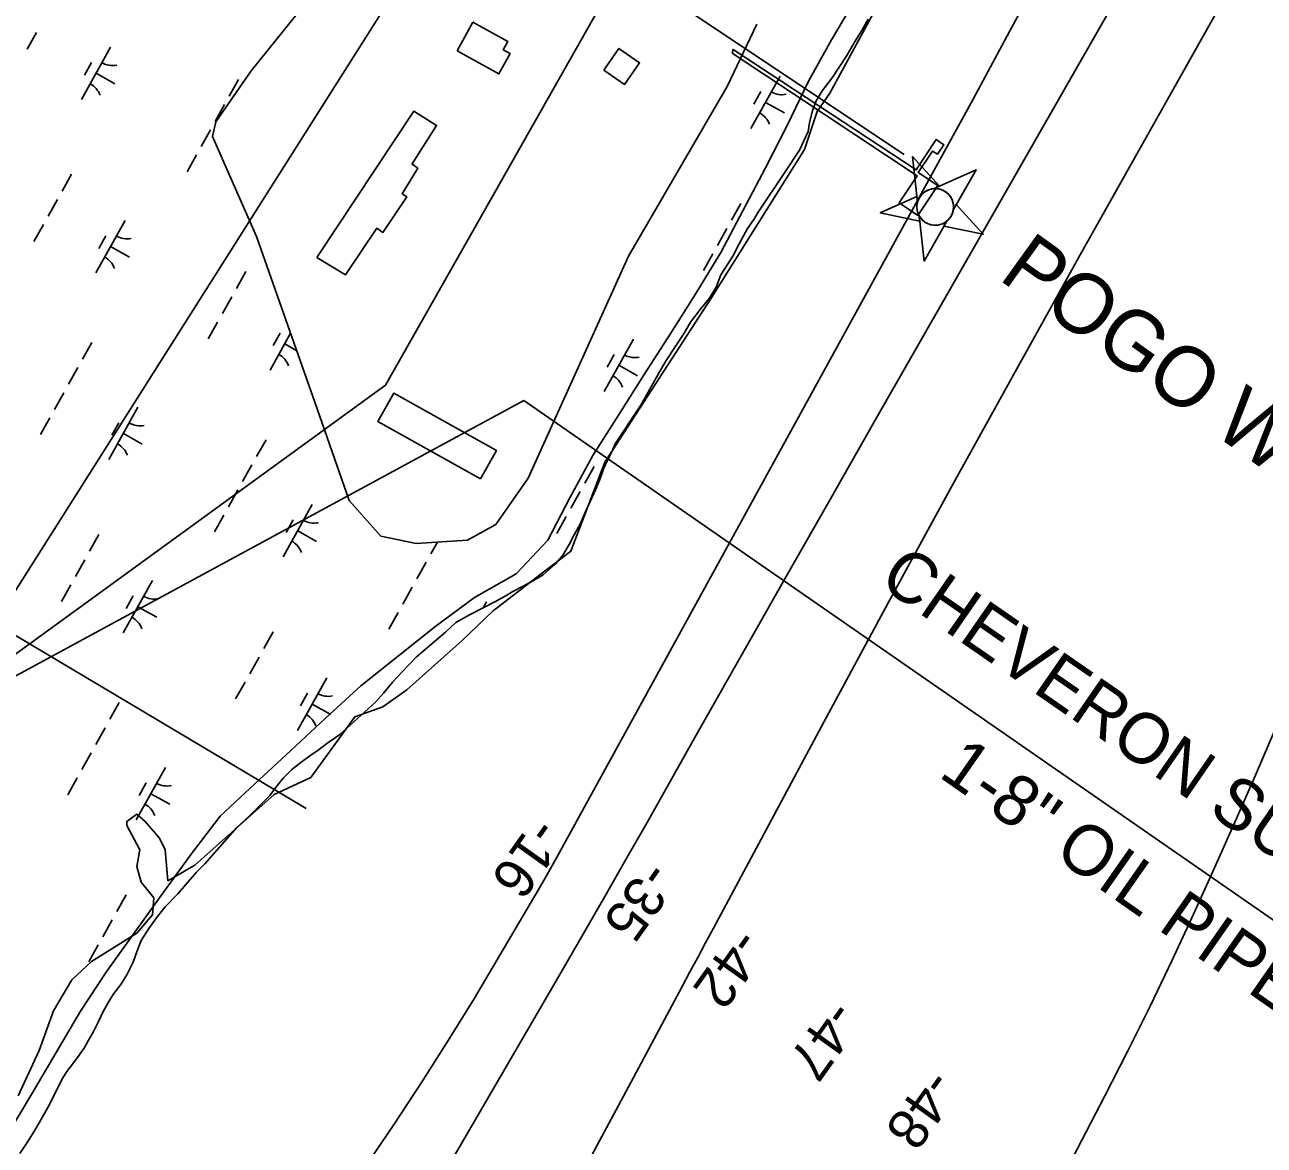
# Model space of a CAD drawing. Extents: x 3923531 to 3943530, y 207391 to 229799.
# Drawn here: x 3934571 to 3935604, y 218928 to 219861 of the extents above; entities that cross this region are included whole.
import ezdxf

# ---------------------------------------------------------------- set-up
doc = ezdxf.new("R2010")
doc.units = 0
for name, color, linetype in [('V-BLDG-OTLN', 7, 'Continuous'), ('V-CHAN-DOCK', 7, 'Continuous'), ('V-CHAN-NAID', 7, 'Continuous'), ('V-GRID-MAJR', 7, 'Continuous'), ('V-RIVR-EDGE', 7, 'Continuous'), ('V-RIVR-RANG', 7, 'Continuous'), ('V-RRAP-FSHR', 7, 'Continuous'), ('V-TOPO-DPTH', 7, 'Continuous'), ('V-TOPO-MAJR', 7, 'Continuous'), ('V-TOPO-MINR', 7, 'Continuous'), ('V-UTIL-IDEN', 7, 'Continuous'), ('V-UTIL-LINE', 7, 'Continuous'), ('V-WETL-SWMP', 7, 'Continuous')]:
    doc.layers.add(name, color=color, linetype=linetype)

msp = doc.modelspace()

# ---------------------------------------------------------------- linework, layer by layer
at = {"layer": 'V-BLDG-OTLN'}
for points in [[(3934930.9, 219839.7), (3934944, 219863.4), (3934973.2, 219847.3), (3934969.4, 219840.4), (3934975, 219837.3), (3934965.7, 219820.4)], [(3935053.2, 219823.5), (3935065.7, 219841.6), (3935083, 219829.6), (3935070.5, 219811.6)], [(3934814.1, 219667.3), (3934894.8, 219789.3), (3934913.8, 219777.4), (3934893.4, 219745.3), (3934893.5, 219745.1), (3934898.2, 219741.7), (3934885.1, 219720.5), (3934888.9, 219717.8), (3934869, 219688.3), (3934864.1, 219691.7), (3934837.8, 219652.8)], [(3934950.4, 219482.8), (3934864.9, 219530.6), (3934878.1, 219554.2), (3934963.6, 219506.4)]]:
    msp.add_lwpolyline(points, close=True, dxfattribs=at)
at = {"layer": 'V-CHAN-DOCK'}
msp.add_lwpolyline([(3935160.1, 219837.6), (3935314.3, 219735.5), (3935299.3, 219712.8), (3935315, 219702.4), (3935331.5, 219727.5), (3935315.3, 219738.2), (3935327.2, 219756.1), (3935331.3, 219753.5), (3935336.5, 219761.4), (3935330.1, 219765.6), (3935313.6, 219740.4), (3935160.9, 219840.8), (3935160.1, 219837.6)], dxfattribs=at)
at = {"layer": 'V-CHAN-NAID'}
for points in [[(3935314.7, 219713.5), (3935310.5, 219751.5), (3935333, 219726.7), (3935328.6, 219724.8), (3935328, 219724.7), (3935326.9, 219724.6), (3935326, 219724.4), (3935325, 219724.1), (3935324.1, 219723.8), (3935323.2, 219723.5), (3935322.4, 219723.1), (3935321.6, 219722.6), (3935320.8, 219722.1), (3935320, 219721.5), (3935319.4, 219721), (3935318.7, 219720.4), (3935318, 219719.6), (3935317.5, 219719), (3935316.8, 219718.2), (3935316.4, 219717.5), (3935316, 219716.7), (3935315.6, 219716), (3935315.2, 219715.2), (3935314.9, 219714.3)], [(3935344.5, 219707.3), (3935363.5, 219740.5), (3935328.6, 219724.8), (3935329.7, 219724.8), (3935330.6, 219724.7), (3935331.7, 219724.6), (3935332.8, 219724.4), (3935333.4, 219724.2), (3935334.2, 219724), (3935334.9, 219723.8), (3935335.6, 219723.5), (3935336.4, 219723.1), (3935337.1, 219722.7), (3935338, 219722.1), (3935338.7, 219721.7), (3935339.5, 219721), (3935340.2, 219720.3), (3935340.9, 219719.5), (3935341.5, 219718.9), (3935342, 219718.1), (3935342.5, 219717.4), (3935343, 219716.5), (3935343.4, 219715.7), (3935343.7, 219715), (3935343.9, 219714.3), (3935344.2, 219713.4), (3935344.4, 219712.7), (3935344.5, 219711.6), (3935344.6, 219710.8), (3935344.7, 219709.8), (3935344.7, 219708.8), (3935344.6, 219708)], [(3935315.9, 219702.4), (3935316.4, 219697.7), (3935283.6, 219704.5), (3935314.1, 219718.2), (3935314.7, 219713.5), (3935314.5, 219712.6), (3935314.3, 219711.8), (3935314.2, 219710.6), (3935314.1, 219709.6), (3935314.2, 219708.6), (3935314.3, 219707.5), (3935314.4, 219706.5), (3935314.6, 219705.7), (3935314.9, 219704.7), (3935315.2, 219703.9), (3935315.6, 219703)], [(3935344.5, 219707.3), (3935346.9, 219711.4), (3935369.4, 219686.7), (3935336.6, 219693.5), (3935339, 219697.6), (3935339.7, 219698.2), (3935340.4, 219699), (3935341.1, 219699.7), (3935341.8, 219700.5), (3935342.1, 219701), (3935342.5, 219701.7), (3935342.9, 219702.4), (3935343.2, 219703), (3935343.6, 219703.9), (3935343.9, 219704.6), (3935344.1, 219705.4), (3935344.3, 219706.2), (3935344.4, 219706.7)], [(3935339, 219697.6), (3935320.1, 219664.4), (3935315.9, 219702.4), (3935316.3, 219701.7), (3935316.9, 219700.8), (3935317.4, 219700.1), (3935318.1, 219699.3), (3935318.7, 219698.6), (3935319.3, 219698.1), (3935320.1, 219697.4), (3935320.7, 219696.9), (3935321.7, 219696.3), (3935322.6, 219695.9), (3935323.6, 219695.4), (3935324.4, 219695.1), (3935325.5, 219694.7), (3935326.6, 219694.5), (3935327.7, 219694.3), (3935328.4, 219694.3), (3935329.5, 219694.2), (3935330.5, 219694.3), (3935331.6, 219694.4), (3935332.6, 219694.6), (3935333.5, 219694.8), (3935334.5, 219695.1), (3935335.6, 219695.5), (3935336.5, 219696), (3935337.5, 219696.5), (3935338.1, 219697)]]:
    msp.add_lwpolyline(points, close=True, dxfattribs=at)
msp.add_circle((3935329.4, 219709.5), 15.3, dxfattribs=at)
at = {"layer": 'V-GRID-MAJR'}
msp.add_spline([(3935779.9, 210874.8), (3935760.8, 211942.6), (3935652.4, 218002.6), (3935544, 224062.6), (3935501.8, 226418.9)], degree=3, dxfattribs=at)
at = {"layer": 'V-RIVR-EDGE'}
msp.add_lwpolyline([(3935282.8, 219879.9), (3935241.5, 219804.4), (3935230.9, 219789.1), (3935220.3, 219757.3), (3935142.5, 219633.5), (3935093, 219556.9), (3935054.1, 219496.8), (3935025.8, 219422.5), (3934996.3, 219400.1), (3934961, 219373), (3934935, 219348.3), (3934889.1, 219307), (3934869, 219292.9), (3934845.5, 219284.6), (3934808.9, 219233.9), (3934778.3, 219219.8), (3934712.3, 219160.9), (3934689.9, 219147.9), (3934687.5, 219173.8), (3934682.8, 219183.3), (3934671, 219197.4), (3934663.9, 219203.3), (3934655.7, 219197.4), (3934655.7, 219193.9), (3934666.3, 219173.8), (3934663.9, 219159.7), (3934667.5, 219146.7), (3934678.1, 219133.7), (3934676.9, 219119.6), (3934663.9, 219104.3), (3934626.2, 219080.7), (3934609.7, 219065.4), (3934594.4, 219039.5), (3934582.6, 219006.4), (3934564.9, 218968.7)], dxfattribs=at)
at = {"layer": 'V-RRAP-FSHR'}
for points in [[(3935263.3, 219883.2), (3935242.8, 219848.9), (3935223.5, 219813.9), (3935206.3, 219777.8), (3935187.9, 219742.2), (3935169.3, 219706.8), (3935150.7, 219671.4), (3935129.9, 219637.3), (3935108.4, 219603.6), (3935086.9, 219569.9), (3935065.4, 219536.1), (3935043.9, 219502.4), (3935024.9, 219467.2), (3935006.4, 219431.8), (3934980.2, 219403.7), (3934945.4, 219383.9), (3934913.3, 219360.3), (3934882, 219335.3), (3934850.7, 219310.4), (3934821.2, 219283.4), (3934791.9, 219256.2), (3934762.6, 219229), (3934733.3, 219201.8), (3934709.1, 219170), (3934685.7, 219137.6), (3934662.3, 219105.1), (3934638.9, 219072.7), (3934617.1, 219039.2), (3934596.7, 219004.8), (3934576.3, 218970.4)], [(3934576.3, 218970.4), (3934555.9, 218936)]]:
    msp.add_lwpolyline(points, dxfattribs=at)
at = {"layer": 'V-TOPO-DPTH'}
for points in [[(3935591.6, 219921.4), (3935451.6, 219672), (3935397.3, 219574.6), (3935343.3, 219476.9), (3935289.9, 219378.9), (3935236.9, 219280.8), (3935144.6, 219108.5), (3935138, 219096.3), (3935131.5, 219084.1), (3935124.9, 219071.9), (3935118.4, 219059.7), (3935071.5, 218972.1), (3935041.5, 218916.1), (3935011.7, 218860.1), (3934981.8, 218804), (3934952.1, 218747.9), (3934930.6, 218707.3), (3934890.6, 218630.7), (3934851.1, 218553.8), (3934812.4, 218476.5), (3934774.2, 218398.9), (3934674.5, 218193.5), (3934122.2, 217382.8)], [(3934122.2, 217382.8), (3934674.5, 218193.5), (3934774.2, 218398.9), (3934812.4, 218476.5), (3934851.1, 218553.8), (3934890.6, 218630.7), (3934930.6, 218707.3), (3934952.1, 218747.9), (3934981.8, 218804), (3935011.7, 218860.1), (3935041.5, 218916.1), (3935071.5, 218972.1), (3935118.4, 219059.7), (3935124.9, 219071.9), (3935131.5, 219084.1), (3935138, 219096.3), (3935144.6, 219108.5), (3935236.9, 219280.8), (3935289.9, 219378.9), (3935343.3, 219476.9), (3935397.3, 219574.6), (3935451.6, 219672), (3935591.6, 219921.4)], [(3934555.8, 218313), (3934642.8, 218446.8), (3934696, 218529.9), (3934748.3, 218613.5), (3934799.4, 218697.9), (3934849.6, 218782.8), (3935018.5, 219073.2), (3935036.3, 219104), (3935054, 219134.8), (3935071.6, 219165.7), (3935089.2, 219196.6), (3935129.1, 219267.2), (3935166.5, 219333.4), (3935204.1, 219399.6), (3935241.7, 219465.7), (3935279.4, 219531.8), (3935501.8, 219920.9)], [(3934555.8, 218313), (3934642.8, 218446.8), (3934696, 218529.9), (3934748.3, 218613.5), (3934799.4, 218697.9), (3934849.6, 218782.8), (3935018.5, 219073.2), (3935036.3, 219104), (3935054, 219134.8), (3935071.6, 219165.7), (3935089.2, 219196.6), (3935129.1, 219267.2), (3935166.5, 219333.4), (3935204.1, 219399.6), (3935241.7, 219465.7), (3935279.4, 219531.8), (3935501.8, 219920.9)], [(3935421.8, 219912.1), (3935391.4, 219855.6), (3935360.9, 219799.3), (3935330.1, 219743.1), (3935018.3, 219175.2), (3935013.4, 219166.4), (3935008.5, 219157.6), (3935003.5, 219148.8), (3934998.4, 219140.1), (3934966.6, 219085.8), (3934945.3, 219050.2), (3934923.5, 219014.8), (3934901.1, 218979.9), (3934878.3, 218945.2), (3934862.6, 218921.7), (3934831.5, 218875.5), (3934800.4, 218829.3), (3934769.1, 218783.2), (3934737.8, 218737.2), (3934488.5, 218371.8)]]:
    msp.add_lwpolyline(points, dxfattribs=at)
at = {"layer": 'V-TOPO-MAJR'}
msp.add_lwpolyline([(3935613.1, 219274.9), (3935596.4, 219236), (3935579.5, 219197.2), (3935562.2, 219158.6), (3935544.8, 219120), (3935526.9, 219081.7), (3935508.6, 219043.5), (3935489.7, 219005.6), (3935470.4, 218968), (3935436.2, 218902.2)], dxfattribs=at)
at = {"layer": 'V-TOPO-MINR'}
for points in [[(3935591.6, 219921.4), (3935451.6, 219672), (3935397.3, 219574.6), (3935343.3, 219476.9), (3935289.9, 219378.9), (3935236.9, 219280.8), (3935144.6, 219108.5), (3935138, 219096.3), (3935131.5, 219084.1), (3935124.9, 219071.9), (3935118.4, 219059.7), (3935071.5, 218972.1), (3935041.5, 218916.1), (3935011.7, 218860.1), (3934981.8, 218804), (3934952.1, 218747.9), (3934930.6, 218707.3), (3934890.6, 218630.7), (3934851.1, 218553.8), (3934812.4, 218476.5), (3934774.2, 218398.9), (3934674.5, 218193.5), (3934122.2, 217382.8)], [(3935501.8, 219920.9), (3935279.4, 219531.8), (3935241.7, 219465.7), (3935204.1, 219399.6), (3935166.5, 219333.4), (3935129.1, 219267.2), (3935089.2, 219196.6), (3935071.6, 219165.7), (3935054, 219134.8), (3935036.3, 219104), (3935018.5, 219073.2), (3934849.6, 218782.8), (3934799.4, 218697.9), (3934748.3, 218613.5), (3934696, 218529.9), (3934642.8, 218446.8), (3934555.8, 218313)], [(3935421.8, 219912.1), (3935391.4, 219855.6), (3935360.9, 219799.3), (3935330.1, 219743.1), (3935018.3, 219175.2), (3935013.4, 219166.4), (3935008.5, 219157.6), (3935003.5, 219148.8), (3934998.4, 219140.1), (3934966.6, 219085.8), (3934945.3, 219050.2), (3934923.5, 219014.8), (3934901.1, 218979.9), (3934878.3, 218945.2), (3934862.6, 218921.7), (3934831.5, 218875.5), (3934800.4, 218829.3), (3934769.1, 218783.2), (3934737.8, 218737.2), (3934488.5, 218371.8)]]:
    msp.add_lwpolyline(points, dxfattribs=at)
at = {"layer": 'V-UTIL-LINE'}
for points in [[(3936636.4, 224015.9), (3936525.6, 224056.2), (3935321.3, 220766.2), (3935347.7, 220401.8), (3934871.3, 219561.1), (3934439.5, 219247.4), (3932085.9, 216616.8), (3928247.6, 212430.3)], [(3934948.1, 219998.5), (3933937.9, 218403.6), (3930512.9, 214727.6), (3928293.6, 212405.3)], [(3935090.4, 219895.4), (3935303.6, 219753.2)], [(3936739.3, 218357.7), (3936622.1, 218414.6), (3934986.4, 219548.1), (3933485.3, 218734.8), (3932852, 218820.9)], [(3928303.7, 212396.8), (3930529.6, 214712.5), (3934263.4, 218684.8), (3934306.8, 218941.8), (3934562.1, 219352.8), (3934805.1, 219208.2)]]:
    msp.add_lwpolyline(points, dxfattribs=at)
at = {"layer": 'V-WETL-SWMP'}
for p, q in [((3934759.1, 219822.8), (3934884.4, 219978.5)), ((3935268.1, 219856.6), (3935273.4, 219866.1)), ((3935180.6, 219861.8), (3935156, 219810)), ((3935262.2, 219846.7), (3935268.1, 219856.6)), ((3934580.2, 219854.9), (3934572.4, 219841)), ((3935255.6, 219835.8), (3935262.2, 219846.7)), ((3934642.1, 219842.7), (3934617.7, 219799.1)), ((3935249.3, 219826.1), (3935255.6, 219835.8)), ((3934626.1, 219829.9), (3934620.3, 219819.4)), ((3935243.6, 219817.2), (3935249.3, 219826.1)), ((3934629.9, 219820.9), (3934645.6, 219812.1)), ((3934729.9, 219780.3), (3934759.1, 219822.8)), ((3934748.8, 219815.7), (3934741, 219801.7)), ((3935200.1, 219818.5), (3935175.8, 219774.8)), ((3935235.1, 219806.3), (3935243.6, 219817.2)), ((3935156, 219810), (3935073.7, 219668.4)), ((3935184.1, 219805.6), (3935178.3, 219795.2)), ((3935230.2, 219797.8), (3935235.1, 219806.3)), ((3934737.1, 219794.8), (3934729.3, 219780.8)), ((3935188, 219796.6), (3935203.7, 219787.9)), ((3935227, 219789.8), (3935230.2, 219797.8)), ((3935224.7, 219779.7), (3935227, 219789.8)), ((3934725.4, 219773.8), (3934717.6, 219759.8)), ((3934727.1, 219768.3), (3934729.9, 219780.3)), ((3935223.6, 219772.3), (3935224.7, 219779.7)), ((3934763.7, 219685), (3934727.1, 219768.3)), ((3935216.3, 219756.8), (3935223.6, 219772.3)), ((3934713.7, 219752.9), (3934705.9, 219738.9)), ((3935204.3, 219738.8), (3935216.3, 219756.8)), ((3934609.5, 219736.7), (3934601.6, 219722.7)), ((3935181.8, 219705.2), (3935204.3, 219738.8)), ((3934597.7, 219715.7), (3934589.9, 219701.8)), ((3935167.5, 219712.4), (3935159.7, 219698.4)), ((3935178.2, 219699), (3935181.8, 219705.2)), ((3934586, 219694.8), (3934578.2, 219680.8)), ((3934654.1, 219698.3), (3934629.7, 219654.7)), ((3935155.8, 219691.4), (3935148, 219677.5)), ((3935168, 219682.4), (3935172.9, 219691.5)), ((3935172.9, 219691.5), (3935178.2, 219699)), ((3934638.1, 219685.5), (3934632.3, 219675)), ((3934812.4, 219546.8), (3934763.7, 219685)), ((3935166, 219678.8), (3935168, 219682.4)), ((3934641.9, 219676.5), (3934657.7, 219667.7)), ((3935144.1, 219670.5), (3935136.3, 219656.5)), ((3935160.7, 219668.5), (3935166, 219678.8)), ((3935073.7, 219668.4), (3934990.2, 219483.4)), ((3935150.8, 219652.9), (3935156.9, 219662.4)), ((3935156.9, 219662.4), (3935160.7, 219668.5)), ((3934754.7, 219655.6), (3934746.9, 219641.6)), ((3935146.7, 219642.7), (3935150.8, 219652.9)), ((3935141.2, 219633.4), (3935146.7, 219642.7)), ((3934743, 219634.6), (3934735.2, 219620.6)), ((3935133.6, 219623.9), (3935141.2, 219633.4)), ((3935125.5, 219613.5), (3935133.6, 219623.9)), ((3934731.3, 219613.6), (3934723.5, 219599.7)), ((3935120.2, 219604.3), (3935125.5, 219613.5)), ((3934792.1, 219604.3), (3934775, 219573.5)), ((3934783.3, 219604.4), (3934777.5, 219593.9)), ((3935077.8, 219599.4), (3935053.4, 219555.7)), ((3935112.7, 219592.9), (3935120.2, 219604.3)), ((3934626.4, 219596.6), (3934618.6, 219582.7)), ((3934787.2, 219595.4), (3934797.2, 219589.7)), ((3935105.2, 219581.6), (3935112.7, 219592.9)), ((3935061.8, 219586.6), (3935055.9, 219576.1)), ((3935065.6, 219577.6), (3935081.3, 219568.8)), ((3935099.3, 219571.5), (3935105.2, 219581.6)), ((3934614.7, 219575.7), (3934606.9, 219561.7)), ((3935091.6, 219557.6), (3935099.3, 219571.5)), ((3935083.9, 219544.3), (3935091.6, 219557.6)), ((3934603, 219554.7), (3934595.2, 219540.8)), ((3934840.9, 219464.9), (3934812.4, 219546.8)), ((3934664.9, 219542.5), (3934640.6, 219498.9)), ((3935062.6, 219512.2), (3935083.9, 219544.3)), ((3934591.3, 219533.8), (3934583.5, 219519.8)), ((3934648.9, 219529.7), (3934643.1, 219519.2)), ((3934652.7, 219520.7), (3934668.5, 219511.9)), ((3934771.6, 219515.5), (3934763.8, 219501.5)), ((3935056.3, 219498.6), (3935059.8, 219505.3)), ((3935059.8, 219505.3), (3935062.6, 219512.2)), ((3934759.9, 219494.6), (3934752.1, 219480.6)), ((3935053.2, 219491.8), (3935056.3, 219498.6)), ((3935045.1, 219493.3), (3935037.3, 219479.3)), ((3935049.8, 219482.3), (3935053.2, 219491.8)), ((3934748.2, 219473.6), (3934740.4, 219459.6)), ((3934990.2, 219483.4), (3934963.1, 219444.9)), ((3935041.8, 219464), (3935046.3, 219473.7)), ((3935046.3, 219473.7), (3935049.8, 219482.3)), ((3934867.4, 219435.2), (3934840.9, 219464.9)), ((3935033.4, 219472.4), (3935025.6, 219458.4)), ((3935037.5, 219454.9), (3935041.8, 219464)), ((3934810.2, 219461.4), (3934785.8, 219417.8)), ((3935033.4, 219445), (3935037.5, 219454.9)), ((3934736.5, 219452.7), (3934728.7, 219438.7)), ((3934794.1, 219448.6), (3934788.3, 219438.1)), ((3934963.1, 219444.9), (3934939.5, 219431.8)), ((3935021.7, 219451.4), (3935013.9, 219437.4)), ((3935028.5, 219436.2), (3935033.4, 219445)), ((3934632.3, 219436.5), (3934624.5, 219422.5)), ((3934798, 219439.6), (3934813.7, 219430.8)), ((3934896.7, 219428.9), (3934867.4, 219435.2)), ((3935024.3, 219428.1), (3935028.5, 219436.2)), ((3934939.5, 219431.8), (3934896.7, 219428.9)), ((3934914.4, 219430.1), (3934909, 219420.4)), ((3935018.8, 219418.8), (3935024.3, 219428.1)), ((3934620.6, 219415.5), (3934612.8, 219401.5)), ((3934905.1, 219413.4), (3934897.3, 219399.5)), ((3935002.5, 219402.8), (3935012.7, 219411.9)), ((3935012.7, 219411.9), (3935018.8, 219418.8)), ((3934992.7, 219397.1), (3935002.5, 219402.8)), ((3934608.9, 219394.6), (3934601.1, 219380.6)), ((3934677, 219398.1), (3934652.6, 219354.5)), ((3934893.4, 219392.5), (3934885.6, 219378.5)), ((3934977.4, 219388.9), (3934986, 219393.4)), ((3934986, 219393.4), (3934992.7, 219397.1)), ((3934660.9, 219385.3), (3934655.1, 219374.8)), ((3934953.2, 219375.6), (3934962.2, 219380.5)), ((3934962.2, 219380.5), (3934971, 219385)), ((3934971, 219385), (3934977.4, 219388.9)), ((3934664.8, 219376.3), (3934680.5, 219367.5)), ((3934881.7, 219371.5), (3934873.9, 219357.6)), ((3934941.9, 219369.8), (3934953.2, 219375.6)), ((3934955.4, 219380.3), (3934952.6, 219375.3)), ((3934921.3, 219355.2), (3934929.9, 219363.1)), ((3934929.9, 219363.1), (3934941.9, 219369.8)), ((3934777.5, 219355.3), (3934769.7, 219341.4)), ((3934896.7, 219334.2), (3934921.3, 219355.2)), ((3934765.8, 219334.4), (3934758, 219320.4)), ((3934885, 219322.1), (3934896.7, 219334.2)), ((3934877.2, 219313.6), (3934885, 219322.1)), ((3934754.1, 219313.4), (3934746.3, 219299.5)), ((3934822.2, 219317), (3934797.8, 219273.3)), ((3934869.5, 219304.3), (3934877.2, 219313.6)), ((3934806.2, 219304.2), (3934800.3, 219293.7)), ((3934863, 219297), (3934869.5, 219304.3)), ((3934649.2, 219296.4), (3934641.4, 219282.5)), ((3934810, 219295.2), (3934825.7, 219286.4)), ((3934847.9, 219283.2), (3934863, 219297)), ((3934833.1, 219269.8), (3934841.7, 219277.5)), ((3934841.7, 219277.5), (3934847.9, 219283.2)), ((3934637.5, 219275.5), (3934629.7, 219261.5)), ((3934823, 219262.8), (3934833.1, 219269.8)), ((3934808.2, 219252.1), (3934815.2, 219256.9)), ((3934815.2, 219256.9), (3934823, 219262.8)), ((3934625.8, 219254.5), (3934618, 219240.6)), ((3934792.9, 219240.5), (3934800.7, 219246.6)), ((3934800.7, 219246.6), (3934808.2, 219252.1)), ((3934687.8, 219242.3), (3934663.4, 219198.7)), ((3934786.2, 219233.6), (3934792.9, 219240.5)), ((3934614.1, 219233.6), (3934606.3, 219219.6)), ((3934671.8, 219229.5), (3934665.9, 219219)), ((3934774.7, 219219), (3934780.4, 219226.5)), ((3934780.4, 219226.5), (3934786.2, 219233.6)), ((3934675.6, 219220.5), (3934691.3, 219211.7)), ((3934767.1, 219211.1), (3934774.7, 219219)), ((3934758, 219202.2), (3934767.1, 219211.1)), ((3934747.3, 219192.4), (3934758, 219202.2)), ((3934720.7, 219162.1), (3934747.3, 219192.4)), ((3934698.1, 219136.9), (3934713.7, 219155)), ((3934713.7, 219155), (3934720.7, 219162.1)), ((3934655.1, 219136.3), (3934647.3, 219122.3)), ((3934687.6, 219126.2), (3934698.1, 219136.9)), ((3934681.2, 219118.1), (3934687.6, 219126.2)), ((3934643.4, 219115.3), (3934635.6, 219101.3)), ((3934673.9, 219108.2), (3934681.2, 219118.1)), ((3934667.6, 219098.1), (3934673.9, 219108.2)), ((3934631.7, 219094.4), (3934623.9, 219080.4)), ((3934664.1, 219089.4), (3934667.6, 219098.1)), ((3934660.9, 219080), (3934664.1, 219089.4)), ((3934655.8, 219070.1), (3934660.9, 219080)), ((3934644.8, 219053.9), (3934650.7, 219061.6)), ((3934650.7, 219061.6), (3934655.8, 219070.1)), ((3934641.4, 219048.7), (3934644.8, 219053.9)), ((3934635.9, 219039), (3934641.4, 219048.7)), ((3934627.8, 219022.2), (3934632, 219030.7)), ((3934632, 219030.7), (3934635.9, 219039)), ((3934623.5, 219014.6), (3934627.8, 219022.2)), ((3934615.8, 219002.6), (3934620.2, 219009.1)), ((3934620.2, 219009.1), (3934623.5, 219014.6)), ((3934611.1, 218996.2), (3934615.8, 219002.6)), ((3934601.4, 218982.2), (3934605.7, 218988.9)), ((3934605.7, 218988.9), (3934611.1, 218996.2)), ((3934590.8, 218961), (3934601.4, 218982.2)), ((3934582.5, 218946.1), (3934590.8, 218961)), ((3934573, 218930.6), (3934577.2, 218937.4)), ((3934577.2, 218937.4), (3934582.5, 218946.1)), ((3934566.3, 218920.7), (3934573, 218930.6))]:
    msp.add_line(p, q, dxfattribs=at)
for centre, start, end in [((3934643.6, 219844.9), 240.0381, 281.5817), ((3934616.7, 219796.7), 20.0381, 61.5817), ((3935201.6, 219820.6), 240.0381, 281.5817), ((3935174.7, 219772.4), 20.0381, 61.5817), ((3934655.6, 219700.5), 240.0381, 281.5817), ((3934628.7, 219652.3), 20.0381, 61.5817), ((3934800.8, 219619.4), 240.0381, 240.7103), ((3934773.9, 219571.1), 20.0381, 61.5817), ((3935079.2, 219601.5), 240.0381, 281.5817), ((3935052.3, 219553.3), 20.0381, 61.5817), ((3934666.4, 219544.7), 240.0381, 281.5817), ((3934639.5, 219496.5), 20.0381, 61.5817), ((3934811.6, 219463.6), 240.0381, 281.5817), ((3934784.7, 219415.4), 20.0381, 61.5817), ((3934678.4, 219400.3), 240.0381, 281.5817), ((3934651.5, 219352), 20.0381, 61.5817), ((3934823.6, 219319.2), 240.0381, 281.5817), ((3934796.7, 219270.9), 20.0381, 61.5817), ((3934689.2, 219244.5), 240.0381, 281.5817), ((3934662.3, 219196.3), 20.0381, 61.5817)]:
    msp.add_arc(centre, 17.6, start, end, dxfattribs=at)

# ---------------------------------------------------------------- texts
at = {"layer": 'V-CHAN-NAID'}
msp.add_text('POGO W-1 (-4.9)', height=50, rotation=324.301, dxfattribs=at).set_placement((3935381.1, 219649.8))
at = {"layer": 'V-RIVR-RANG'}
for s, rotation, p in [('-16', 234.5983, (3934995.7, 219202.5)), ('-35', 234.3985, (3935089, 219166.4)), ('-42', 234.3985, (3935163.9, 219110.5)), ('-47', 234.3985, (3935242.5, 219050.6)), ('-48', 234.3985, (3935324.2, 218993))]:
    msp.add_text(s, height=33.5, rotation=rotation, dxfattribs=at).set_placement(p)
at = {"layer": 'V-UTIL-IDEN'}
for s, rotation, p in [('CHEVERON SUPPLY PIPELINE', 325.3283, (3935281, 219395)), ('1-8" OIL PIPELINE', 325.0908, (3935331.2, 219235.3))]:
    msp.add_text(s, height=42, rotation=rotation, dxfattribs=at).set_placement(p)

doc.saveas('drawing.dxf')
